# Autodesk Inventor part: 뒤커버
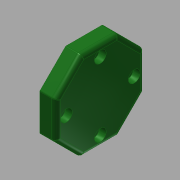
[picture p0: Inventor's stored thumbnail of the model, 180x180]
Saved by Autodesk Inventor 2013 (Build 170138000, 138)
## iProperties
Created: 2015-11
Part Number: 뒤커버
Material: 알루미늄 6061
Document SubType Name: Modeling
Designer: mduedu
Density: 2.71 g/cm^3
Mass: 77.9018 g
Surface Area: 95.5384 cm^2
Volume: 28.746 cm^3
Author: mduedu
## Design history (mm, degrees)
sketch "스케치5" dims "d66" = 60
  geometry: L1 (12.426, 30)-(30, 12.426); L2 (30, 12.426)-(30, -12.426); L3 (30, -12.426)-(12.426, -30); L4 (12.426, -30)-(-12.426, -30); L5 (-12.426, -30)-(-30, -12.426); L6 (-30, -12.426)-(-30, 12.426); L7 (-30, 12.426)-(-12.426, 30); L8 (-12.426, 30)-(12.426, 30); 4 further points
  constraints: 16 end point, 2 coincident, 2 vertical alignment, 1 midpoint, 19 other
extrude "돌출2" new body sketch "스케치5" distance "d67" = 11; taper "d68" = 0 deg
sketch "스케치6"
  geometry: C1 r 16 at (0, 0); 1 further point
  constraints: 1 centre point, 1 coincident
  dimensions: "d69" = 32 diameter of C1
extrude "돌출3" join sketch "스케치6" distance "d70" = 3; taper "d71" = 0 deg
hole "구멍5" diameter "d74" = 25; stored, may be unused: countersink angle "d78" = 90 deg, drill point angle "d80" = 0 deg; dims "d72" = 10, "d73" = 10, "d75" = 6, "d76" = 4, "d77" = 2, "d79" = 10
fillet "모깎기7" dims "d81" = 1
fillet "모깎기8" dims "d82" = 3
fillet "모깎기9" dims "d83" = 3
fillet "모깎기10" dims "d84" = 0.3
sketch "스케치7" dims "d85" = 46
  geometry: 3 further points
  constraints: 2 vertical alignment, 1 coincident, 2 other
hole "구멍6" sketch "스케치7" at (0, 23) diameter "d86" = 4.5; stored, may be unused: countersink angle "d90" = 90 deg, drill point angle "d92" = 0 deg; dims "d87" = 6, "d88" = 8, "d89" = 4.6, "d91" = 10
node "솔리드2"
pattern_circular "원형 패턴3" dims angle "d94" = 360 deg
